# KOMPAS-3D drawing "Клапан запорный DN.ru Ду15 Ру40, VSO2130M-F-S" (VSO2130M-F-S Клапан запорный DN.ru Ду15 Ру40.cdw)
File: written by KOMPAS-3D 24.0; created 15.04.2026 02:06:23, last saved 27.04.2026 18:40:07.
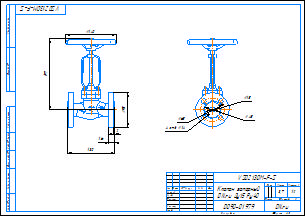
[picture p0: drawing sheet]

Document properties: Автор: DN.ru; Форматы листов документа: A3; Полное имя файла: VSO2130M-F-S Клапан запорный DN.ru Ду15 Ру40.m3d; Масса: 3.7; Наименование: Клапан запорный DN.ru Ду15 Ру40; Количество листов документа: 1; Примечание: D090-01979

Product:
- Part/product: Клапан запорный DN.ru Ду15 Ру40  | designation VSO2130M-F-S
    Масса: 3.7
    Раздел спецификации: Прочие изделия
    Примечание: D090-01979

Views: Вид 1, Вид:1, Проекционный вид 2
Referenced files in C:\Работа\VSO2130M-F-S Клапан запорный DN.ru\DN15\: VSO2130M-F-S DN15 PN40  Клапан запорный сильфонный DN.ru.m3d
Referenced files in C:\Работа\ГОТОВЫЕ ИСХОДНИКИ\VSO2130M-F-S Клапан запорный DN.ru Ду-x Ру40\DN15\: VSO2130M-F-S Клапан запорный DN.ru Ду15 Ру40.m3d
Referenced files in C:\Program Files\ASCON\KOMPAS-3D v24\Templates\: Чертеж_DN.ru.cdt
Referenced files in C:\Работа\ГОТОВЫЕ ИСХОДНИКИ\VSO2130M-F-S Клапан запорный сальниковый DN.ru Ду15-100 Ру40\DN15\: VSO2130M-F-S Клапан запорный DN.ru Ду15 Ру40.m3d
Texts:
  VSO2130M-F-S
  Чертеж_DN.ru.cdt
  Клапан запорный
  DN.ru Ду15 Ру40
  Клапан запорный DN.ru Ду15 Ру40
  VSO2130M-F-S Клапан запорный DN.ru Ду15 Ру40
Dimensions and other numbers on the sheet: 0; 3; 2; 4; 95; 16; 197; 140; 130; 5; 15; 45; 65; 4 отв.; 14; 1:2; 1; 3,7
